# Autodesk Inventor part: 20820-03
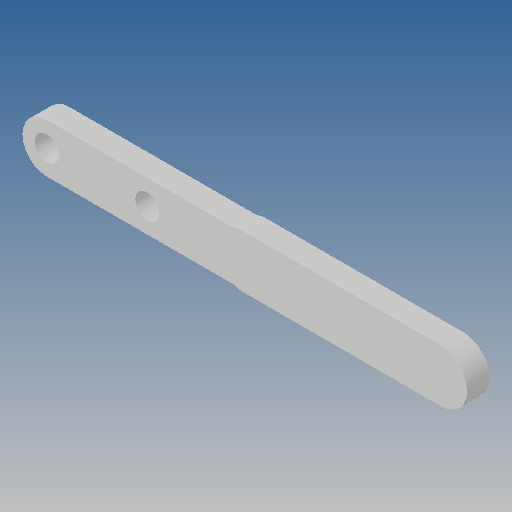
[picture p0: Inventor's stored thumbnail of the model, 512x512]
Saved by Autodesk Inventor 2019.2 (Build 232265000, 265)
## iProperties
Created: 2011-12
Part Number: 20820-03
Material: Ogólny
Document SubType Name: Modeling
Designer: CADENGINEERING4
Density: 1 g/cm^3
Appearance: Domyślna
Author: CADENGINEERING4
Revision Number: ÈÎºÎ
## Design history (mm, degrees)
feature "À­Éì1"
node "Bryła1"
